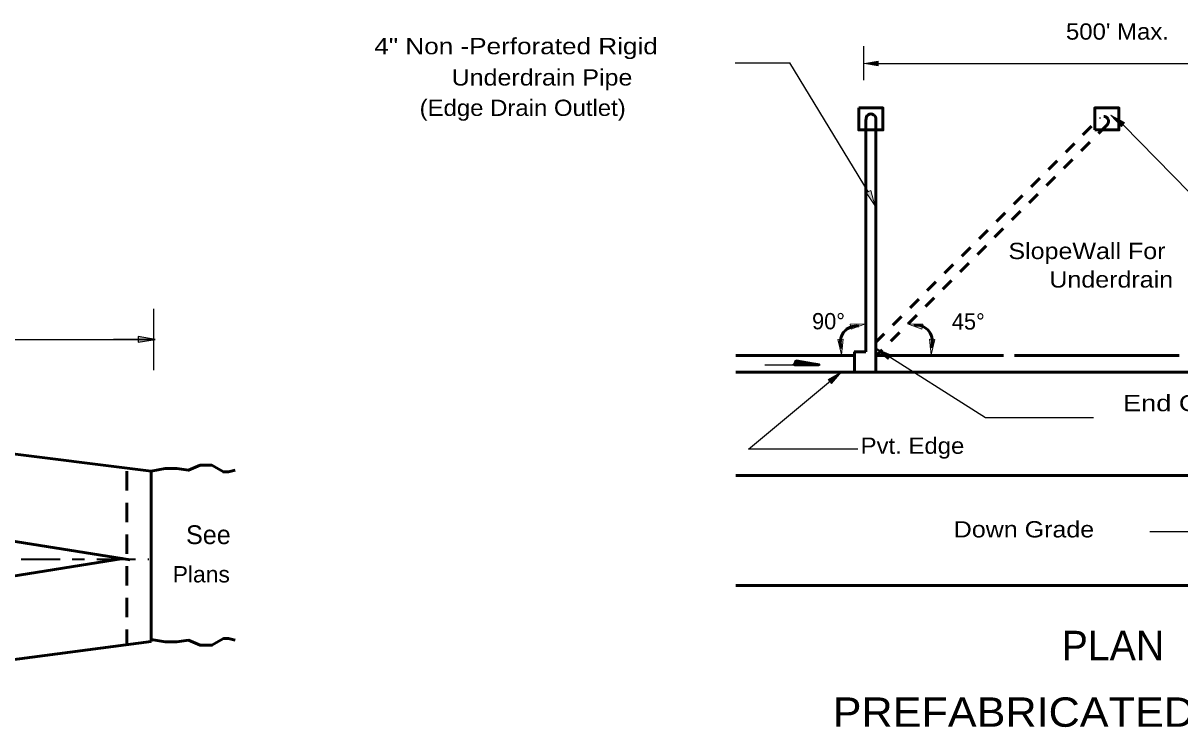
# Model space of a CAD drawing. Extents: x 72.6 to 107.3, y 36.1 to 58.1.
# Drawn here: x 84.21 to 93.67, y 43.14 to 48.93 of the extents above; entities that cross this region are included whole.
import ezdxf

# ---------------------------------------------------------------- set-up
doc = ezdxf.new("R2010")
doc.units = 0
doc.header["$LTSCALE"] = 0.053
for name, pattern in [('DOTTED', [1.5, 0.3, -1.2]), ('LONG_DASH_SHORT_DASH', [9.9, 6, -1.2, 1.5, -1.2]), ('MEDIUM_DASHED', [4.5, 3, -1.5])]:
    doc.linetypes.add(name, pattern=pattern)
doc.layers.add('1', color=7, linetype='Continuous', lineweight=35)
doc.layers.add('3', color=7, linetype='Continuous', lineweight=13)

msp = doc.modelspace()

# ---------------------------------------------------------------- hatches: boundary and pattern name
at = {"layer": '1'}
msp.add_hatch(color=256, dxfattribs=at).paths.add_polyline_path([(85.15325, 46.31858), (85.29392, 46.342), (85.15325, 46.36542)])
msp.add_hatch(color=256, dxfattribs=at).paths.add_polyline_path([(85.15325, 46.31858), (85.29392, 46.342), (85.15325, 46.36542)])
at = {"layer": '3'}
for points in [[(91.20392, 48.61617), (91.20392, 48.57867), (91.09142, 48.59742), (91.09142, 48.59742)], [(93.19317, 48.08317), (93.2185, 48.11633), (93.1065, 48.17575), (93.1065, 48.17575)], [(91.10567, 47.54267), (91.14367, 47.55975), (91.17583, 47.43717), (91.17583, 47.43717)], [(90.97467, 46.46717), (90.98267, 46.42617), (91.10142, 46.47067), (91.10142, 46.47067)], [(91.56967, 46.46717), (91.56167, 46.42617), (91.44292, 46.47067), (91.44292, 46.47067)], [(90.917, 46.3435), (90.87525, 46.34067), (90.90475, 46.21733), (90.90475, 46.21733)], [(91.62508, 46.3435), (91.66683, 46.34067), (91.63733, 46.21733), (91.63733, 46.21733)], [(91.30642, 46.21525), (91.28408, 46.18), (91.18975, 46.26467), (91.18975, 46.26467)], [(90.79583, 46.01467), (90.82233, 45.98242), (90.90567, 46.078), (90.90567, 46.078)]]:
    msp.add_hatch(color=256, dxfattribs=at).paths.add_polyline_path(points)

# ---------------------------------------------------------------- linework, layer by layer
at = {"layer": '1', "lineweight": 25}
for p, q in [((91.08592, 48.46217), (91.08592, 48.73983)), ((91.12392, 48.5975), (94.81142, 48.5975)), ((85.281, 46.09142), (85.281, 46.59233)), ((79.72358, 46.342), (85.27583, 46.342)), ((85.29392, 46.342), (84.95292, 46.342)), ((85.29392, 46.342), (84.95292, 46.342)), ((85.26, 45.266), (85.334, 45.272)), ((85.26, 45.266), (85.334, 45.272))]:
    msp.add_line(p, q, dxfattribs=at)
at = {"layer": '1', "lineweight": 53}
for p, q in [((91.10458, 46.24192), (91.10458, 48.14)), ((91.18558, 48.145), (91.18558, 46.07475)), ((90.03917, 46.21058), (91.00833, 46.21058)), ((91.00833, 46.24175), (91.10458, 46.24175)), ((91.00967, 46.08725), (91.00967, 46.24175)), ((91.18558, 46.21058), (92.22833, 46.21058)), ((92.31867, 46.21058), (93.66517, 46.21058)), ((90.03917, 46.07475), (96.32075, 46.07475)), ((79.7265, 45.94983), (85.26, 45.266)), ((79.7265, 45.38733), (85.0895, 44.54075)), ((85.26, 45.266), (85.26, 43.87275)), ((90.03917, 45.22958), (96.32075, 45.22958)), ((79.7265, 43.70433), (85.03225, 44.55033)), ((90.03917, 44.32958), (96.32075, 44.32958)), ((79.7265, 43.14183), (85.26, 43.87275))]:
    msp.add_line(p, q, dxfattribs=at)
at = {"layer": '1', "linetype": 'DOTTED', "lineweight": 53}
for p, q in [((91.18175, 46.31717), (93.01575, 48.15117)), ((93.07575, 48.09667), (91.19383, 46.21475))]:
    msp.add_line(p, q, dxfattribs=at)
at = {"layer": '1'}
msp.add_line((93.01767, 48.15317), (93.01842, 48.15392), dxfattribs=at)
at = {"layer": '1', "linetype": 'MEDIUM_DASHED', "lineweight": 53}
msp.add_line((85.06083, 45.266), (85.06083, 43.85358), dxfattribs=at)
at = {"layer": '1', "linetype": 'LONG_DASH_SHORT_DASH'}
msp.add_line((76.78117, 44.54583), (85.24208, 44.54583), dxfattribs=at)
at = {"layer": '1', "lineweight": 53}
for points in [[(91.046, 48.23542), (91.24308, 48.23542), (91.24308, 48.05467), (91.046, 48.05467)], [(92.97533, 48.05475), (93.17233, 48.05475), (93.17233, 48.2355), (92.97533, 48.2355)]]:
    msp.add_lwpolyline(points, close=True, dxfattribs=at)
at = {"layer": '1', "lineweight": 25}
msp.add_lwpolyline([(85.15325, 46.31858), (85.29392, 46.342), (85.15325, 46.36542)], close=True, dxfattribs=at)
msp.add_lwpolyline([(85.15325, 46.31858), (85.29392, 46.342), (85.15325, 46.36542)], close=True, dxfattribs=at)
msp.add_lwpolyline([(90.27792, 46.134), (90.73058, 46.134), (90.53417, 46.16875), (90.51742, 46.13458), (90.50267, 46.13408)], dxfattribs=at)
at = {"layer": '1', "lineweight": 53}
for points in [[(90.51883, 46.13525), (90.53433, 46.16683), (90.72033, 46.13525), (90.51933, 46.13525), (90.53492, 46.16575), (90.70942, 46.13633), (90.52225, 46.13633), (90.53542, 46.16458), (90.69842, 46.13758), (90.5245, 46.13692), (90.53608, 46.16292), (90.68692, 46.13867), (90.52342, 46.13633), (90.53492, 46.16058), (90.6765, 46.13983), (90.52683, 46.13867), (90.53542, 46.15883), (90.66333, 46.1415), (90.52625, 46.13808), (90.53608, 46.1565), (90.65175, 46.14333), (90.52917, 46.13983), (90.53667, 46.15483), (90.63967, 46.14383), (90.5315, 46.14042), (90.53775, 46.1525), (90.627, 46.14442), (90.53375, 46.1415), (90.53892, 46.15075), (90.60517, 46.14558), (90.53775, 46.14275), (90.53892, 46.1485), (90.58617, 46.14675), (90.54067, 46.14383), (90.54067, 46.14617), (90.56142, 46.14733), (90.54408, 46.14442), (90.52742, 46.13808), (90.53375, 46.15192), (90.65067, 46.14333), (90.56142, 46.13925), (90.53892, 46.13983), (90.532, 46.13925), (90.53608, 46.15025), (90.53842, 46.15308), (90.65292, 46.14275), (90.67133, 46.1415)], [(85.26, 45.266), (85.37483, 45.28567), (85.47008, 45.28567), (85.56542, 45.272), (85.66067, 45.31292), (85.756, 45.31292), (85.85125, 45.25842), (85.89208, 45.25842), (85.94658, 45.272)], [(85.26, 45.266), (85.37483, 45.28567), (85.47008, 45.28567), (85.56542, 45.272), (85.66067, 45.31292), (85.756, 45.31292), (85.85125, 45.25842), (85.89208, 45.25842), (85.94658, 45.272)], [(85.26, 43.889), (85.37483, 43.86933), (85.47008, 43.86933), (85.56542, 43.883), (85.66067, 43.84208), (85.756, 43.84208), (85.85125, 43.89658), (85.89208, 43.89658), (85.94658, 43.883)], [(85.26, 43.889), (85.37483, 43.86933), (85.47008, 43.86933), (85.56542, 43.883), (85.66067, 43.84208), (85.756, 43.84208), (85.85125, 43.89658), (85.89208, 43.89658), (85.94658, 43.883)]]:
    msp.add_lwpolyline(points, dxfattribs=at)
for centre, radius, start, end in [((91.1451, 48.14503), 0.0405, 352.63783, 187.17803), ((91.02675, 46.32012), 0.13242, 81.70626, 203.77642), ((91.51525, 46.32712), 0.13242, 336.22357, 98.29374)]:
    msp.add_arc(centre, radius, start, end, dxfattribs=at)
at = {"layer": '1'}
msp.add_arc((93.0471, 48.12526), 0.04049, 136.63203, 140.96336, dxfattribs=at)
at = {"layer": '1', "linetype": 'DOTTED', "lineweight": 53}
msp.add_arc((93.0471, 48.12526), 0.04049, 305.12086, 136.088, dxfattribs=at)
at = {"layer": '3', "lineweight": 25}
for p, q in [((90.03467, 48.60492), (90.48067, 48.60492)), ((91.12625, 47.54658), (90.48067, 48.60492)), ((94.54842, 46.72575), (93.206, 48.09758)), ((92.08225, 45.70167), (91.19542, 46.2635)), ((90.14283, 45.44508), (90.89483, 46.07092)), ((92.96492, 45.70167), (92.08225, 45.70167)), ((92.96492, 45.70167), (92.08225, 45.70167)), ((91.0255, 45.44508), (90.14283, 45.44508)), ((91.038, 45.44508), (90.15533, 45.44508)), ((94.30883, 44.77008), (93.42617, 44.77008))]:
    msp.add_line(p, q, dxfattribs=at)
at = {"layer": '3'}
for points in [[(91.20392, 48.61617), (91.20392, 48.57867), (91.09142, 48.59742), (91.09142, 48.59742)], [(93.19317, 48.08317), (93.2185, 48.11633), (93.1065, 48.17575), (93.1065, 48.17575)], [(91.10567, 47.54267), (91.14367, 47.55975), (91.17583, 47.43717), (91.17583, 47.43717)], [(90.97467, 46.46717), (90.98267, 46.42617), (91.10142, 46.47067), (91.10142, 46.47067)], [(91.56967, 46.46717), (91.56167, 46.42617), (91.44292, 46.47067), (91.44292, 46.47067)], [(90.917, 46.3435), (90.87525, 46.34067), (90.90475, 46.21733), (90.90475, 46.21733)], [(91.62508, 46.3435), (91.66683, 46.34067), (91.63733, 46.21733), (91.63733, 46.21733)], [(91.30642, 46.21525), (91.28408, 46.18), (91.18975, 46.26467), (91.18975, 46.26467)], [(90.79583, 46.01467), (90.82233, 45.98242), (90.90567, 46.078), (90.90567, 46.078)]]:
    msp.add_lwpolyline(points, close=True, dxfattribs=at)

# ---------------------------------------------------------------- texts
for s, height, width, p in [("500' Max.", 0.133, 1.1, (92.7395, 48.79325)), ('4" Non -Perforated Rigid', 0.133, 1.2, (87.0845, 48.67375)), ('Underdrain Pipe', 0.133, 1.15, (87.7165, 48.41808)), ('(Edge Drain Outlet)', 0.133, 1.1, (87.45492, 48.1695)), (' SlopeWall For ', 0.133, 1.15, (92.21233, 46.99908)), ('Underdrain', 0.133, 1.15, (92.60383, 46.76617)), ('End Of Edge Drain To Be Capped', 0.133, 1.25, (93.20575, 45.755)), ('Pvt. Edge', 0.133, 1.1, (91.06067, 45.40692)), ('Down Grade', 0.133, 1.15, (91.822, 44.72325)), ('Plans', 0.133, 1.05, (85.43617, 44.35558)), ('Plans', 0.133, 1.05, (85.43617, 44.35558)), ('PREFABRICATED EDGE DRAIN', 0.24, 1.1, (90.83225, 43.17533))]:
    msp.add_text(s, height=height, dxfattribs=dict(at, width=width)).set_placement(p)
for s, height, p in [('90°', 0.133, (90.66375, 46.425)), ('45°', 0.133, (91.80675, 46.42267)), ('See', 0.1536, (85.54508, 44.66883)), ('PLAN', 0.24, (92.70458, 43.71983))]:
    msp.add_text(s, height=height, dxfattribs=at).set_placement(p)

doc.saveas('drawing.dxf')
